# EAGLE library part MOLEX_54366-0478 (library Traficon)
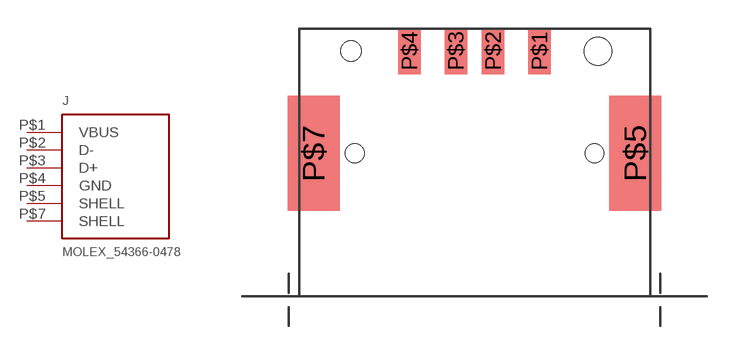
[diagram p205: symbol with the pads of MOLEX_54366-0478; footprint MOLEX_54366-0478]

Designator prefix J

## MOLEX_54366-0478  [MOLEX_54366-0478]
P$1  VBUS  pwr
P$2  D-
P$3  D+
P$4  GND  pwr
P$5  SHELL  pas
P$7  SHELL  pas

## Footprint MOLEX_54366-0478 (pad centres in mm)
smd 1.2 x 2.5: P$1 3.5,0; P$2 1,0; P$3 -1,0; P$4 -3.5,0
smd 2.8 x 6.2: P$5 8.652,-5.507; P$7 -8.663,-5.51
hole 1.5 at 6.65,0
hole 1.1 at -6.65,0
hole 1 at -6.45,-5.5
hole 1 at 6.45,-5.5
